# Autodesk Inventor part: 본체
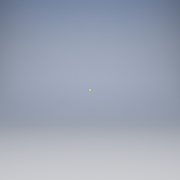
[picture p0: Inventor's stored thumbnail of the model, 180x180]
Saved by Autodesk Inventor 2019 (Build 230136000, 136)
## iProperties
Created: 2022-03
Part Number: 본체
Material: 일반
Document SubType Name: Modeling
Designer: LINE501-3
Density: 1 g/cm^3
Appearance: 기본값
Author: LINE501-3
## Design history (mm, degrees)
sketch "스케치18"
  geometry: 1 further point
  constraints: 1 other
node "솔리드1"
